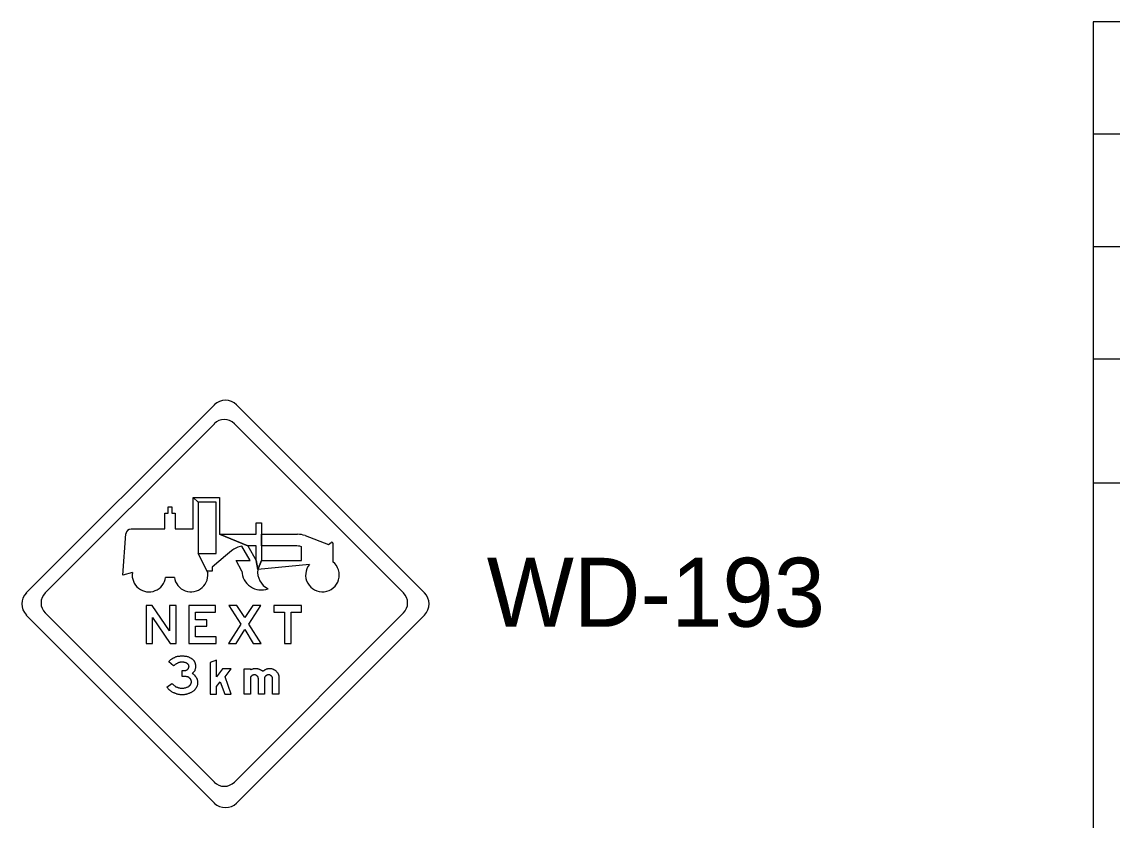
# Model space of a CAD drawing. Extents: x 1342 to 1558, y 178 to 457.
# Drawn here: x 1450.61 to 1485.03, y 224.55 to 249.75 of the extents above; entities that cross this region are included whole.
import ezdxf

# ---------------------------------------------------------------- set-up
doc = ezdxf.new("R2010")
doc.units = 0
for name, color, linetype in [('Level 1', 7, 'Continuous'), ('Level 10', 7, 'Continuous'), ('Level 44', 7, 'Continuous'), ('Level 63', 7, 'Continuous')]:
    doc.layers.add(name, color=color, linetype=linetype)

msp = doc.modelspace()

# ---------------------------------------------------------------- linework, layer by layer
at = {"layer": 'Level 1'}
for p, q in [((1484.439, 188.732), (1484.439, 235.196)), ((1455.229, 234.235), (1455.229, 234.439)), ((1455.229, 234.439), (1455.35, 234.439)), ((1455.35, 234.439), (1455.35, 234.235)), ((1456.018, 233.738), (1456.018, 234.733)), ((1456.018, 234.733), (1456.181, 234.582)), ((1456.181, 234.582), (1456.018, 234.733)), ((1456.018, 234.733), (1456.847, 234.733)), ((1456.181, 234.582), (1456.181, 232.966)), ((1456.743, 234.582), (1456.181, 234.582)), ((1456.743, 232.966), (1456.743, 234.582)), ((1456.847, 234.733), (1456.847, 233.571)), ((1455.122, 233.738), (1455.122, 234.235)), ((1455.122, 234.235), (1455.229, 234.235)), ((1455.35, 234.235), (1455.454, 234.235)), ((1455.454, 234.235), (1455.454, 233.738)), ((1454.063, 233.738), (1455.122, 233.738)), ((1455.454, 233.738), (1456.018, 233.738)), ((1458.01, 233.571), (1458.01, 233.93)), ((1458.01, 233.93), (1458.175, 233.93)), ((1458.175, 233.93), (1458.175, 233.571)), ((1453.795, 232.285), (1453.897, 233.585)), ((1456.847, 233.571), (1457.744, 233.202)), ((1457.744, 233.202), (1456.847, 233.571)), ((1456.847, 233.571), (1458.01, 233.571)), ((1458.175, 233.206), (1458.175, 233.571)), ((1458.175, 233.571), (1459.314, 233.571)), ((1458.175, 233.571), (1458.175, 233.206)), ((1459.55, 233.528), (1460.295, 233.244)), ((1457.232, 233.051), (1457.036, 232.887)), ((1457.818, 232.742), (1457.555, 233.198)), ((1458.01, 233.206), (1457.741, 233.206)), ((1457.741, 233.206), (1457.744, 233.202)), ((1457.744, 233.202), (1458.01, 232.742)), ((1458.01, 232.742), (1458.01, 233.206)), ((1459.246, 233.206), (1458.175, 233.206)), ((1458.175, 233.206), (1458.175, 232.742)), ((1459.436, 232.742), (1459.436, 233.181)), ((1460.295, 233.244), (1460.377, 233.312)), ((1460.431, 233.286), (1460.431, 232.7)), ((1456.181, 232.966), (1456.477, 232.359)), ((1456.477, 232.359), (1456.181, 232.966)), ((1456.181, 232.966), (1456.743, 232.966)), ((1457.036, 232.887), (1456.615, 232.533)), ((1457.554, 232.41), (1457.371, 232.742)), ((1457.371, 232.742), (1457.818, 232.742)), ((1458.01, 232.742), (1458.055, 232.459)), ((1458.055, 232.459), (1458.01, 232.742)), ((1458.055, 232.459), (1458.175, 232.742)), ((1458.175, 232.742), (1458.055, 232.459)), ((1458.175, 232.742), (1459.436, 232.742)), ((1454.099, 232.363), (1453.795, 232.285)), ((1456.615, 232.41), (1456.468, 232.41)), ((1456.615, 232.533), (1456.615, 232.41)), ((1459.687, 232.62), (1458.055, 232.459)), ((1455.426, 232.211), (1455.15, 232.211))]:
    msp.add_line(p, q, dxfattribs=at)
for points in [[(1454.531, 231.319), (1454.531, 230.124), (1454.738, 230.124), (1454.738, 230.943), (1455.293, 230.124), (1455.481, 230.124), (1455.481, 231.319), (1455.274, 231.319), (1455.274, 230.52), (1454.729, 231.319), (1454.531, 231.319)], [(1455.886, 231.319), (1455.886, 230.124), (1456.741, 230.124), (1456.741, 230.331), (1456.093, 230.331), (1456.093, 230.67), (1456.45, 230.67), (1456.45, 230.868), (1456.093, 230.868), (1456.093, 231.112), (1456.722, 231.112), (1456.722, 231.319), (1455.886, 231.319)], [(1457.146, 231.319), (1457.522, 230.736), (1457.136, 230.124), (1457.381, 230.124), (1457.653, 230.567), (1457.917, 230.124), (1458.161, 230.124), (1457.776, 230.736), (1458.152, 231.319), (1457.898, 231.319), (1457.653, 230.943), (1457.399, 231.319), (1457.146, 231.319)], [(1458.566, 231.319), (1458.566, 231.112), (1458.904, 231.112), (1458.904, 230.124), (1459.111, 230.124), (1459.111, 231.112), (1459.441, 231.112), (1459.441, 231.319), (1458.566, 231.319)], [(1455.247, 229.55), (1455.257, 229.569), (1455.275, 229.578), (1455.285, 229.587), (1455.304, 229.607), (1455.313, 229.616), (1455.332, 229.625), (1455.35, 229.635), (1455.36, 229.644), (1455.379, 229.663), (1455.398, 229.673), (1455.416, 229.673), (1455.426, 229.682), (1455.445, 229.691), (1455.463, 229.7), (1455.482, 229.71), (1455.501, 229.71), (1455.52, 229.719), (1455.539, 229.719), (1455.557, 229.728), (1455.576, 229.728), (1455.595, 229.728), (1455.614, 229.738), (1455.633, 229.738), (1455.652, 229.738), (1455.67, 229.738), (1455.689, 229.738), (1455.708, 229.738), (1455.727, 229.738), (1455.745, 229.728), (1455.764, 229.728), (1455.783, 229.728), (1455.802, 229.719), (1455.811, 229.719), (1455.83, 229.71), (1455.849, 229.71), (1455.868, 229.7), (1455.887, 229.691), (1455.905, 229.682), (1455.924, 229.673), (1455.934, 229.673), (1455.952, 229.663)], [(1455.952, 229.663), (1455.962, 229.653), (1455.98, 229.644), (1455.99, 229.635), (1456, 229.625), (1456.009, 229.616), (1456.018, 229.607), (1456.028, 229.597), (1456.037, 229.587), (1456.046, 229.578), (1456.046, 229.559), (1456.056, 229.55), (1456.066, 229.541), (1456.075, 229.531), (1456.075, 229.512), (1456.084, 229.503), (1456.084, 229.484), (1456.084, 229.475), (1456.093, 229.466), (1456.093, 229.446), (1456.093, 229.437), (1456.093, 229.418), (1456.093, 229.409), (1456.093, 229.39), (1456.093, 229.38), (1456.093, 229.362), (1456.093, 229.352), (1456.093, 229.343), (1456.084, 229.324), (1456.084, 229.314), (1456.075, 229.296), (1456.075, 229.287), (1456.066, 229.277), (1456.066, 229.259), (1456.056, 229.249), (1456.046, 229.239), (1456.037, 229.23), (1456.028, 229.221), (1456.018, 229.202), (1456.009, 229.193), (1456, 229.183), (1455.99, 229.173)], [(1455.398, 229.418), (1455.247, 229.55)], [(1455.811, 229.503), (1455.793, 229.512), (1455.783, 229.512), (1455.764, 229.521), (1455.755, 229.521), (1455.736, 229.521), (1455.727, 229.531), (1455.708, 229.531), (1455.698, 229.531), (1455.68, 229.531), (1455.67, 229.531), (1455.652, 229.531), (1455.633, 229.531), (1455.623, 229.531), (1455.604, 229.531), (1455.595, 229.521), (1455.576, 229.521), (1455.567, 229.521), (1455.548, 229.512), (1455.539, 229.503), (1455.52, 229.503), (1455.511, 229.494), (1455.492, 229.484), (1455.482, 229.484), (1455.473, 229.475), (1455.454, 229.466), (1455.445, 229.456), (1455.435, 229.446), (1455.426, 229.437), (1455.416, 229.428), (1455.398, 229.418)], [(1455.793, 229.08), (1455.67, 229.08), (1455.67, 229.277), (1455.764, 229.277)], [(1455.764, 229.277), (1455.774, 229.277), (1455.783, 229.277), (1455.793, 229.287), (1455.802, 229.287), (1455.811, 229.287), (1455.821, 229.296), (1455.83, 229.296), (1455.839, 229.305), (1455.849, 229.314), (1455.849, 229.324), (1455.859, 229.324), (1455.868, 229.334), (1455.868, 229.343), (1455.868, 229.352), (1455.877, 229.352), (1455.877, 229.362), (1455.877, 229.371), (1455.877, 229.38), (1455.877, 229.39), (1455.887, 229.4), (1455.877, 229.409), (1455.877, 229.418), (1455.877, 229.428), (1455.877, 229.437), (1455.868, 229.446), (1455.868, 229.456), (1455.859, 229.456), (1455.859, 229.466), (1455.849, 229.475), (1455.849, 229.484), (1455.839, 229.484), (1455.83, 229.494), (1455.821, 229.494), (1455.821, 229.503), (1455.811, 229.503)], [(1456.752, 229.597), (1456.555, 229.521), (1456.555, 228.525), (1456.752, 228.525), (1456.752, 228.769), (1456.874, 228.911), (1457.015, 228.525), (1457.222, 228.525), (1457.024, 229.07), (1457.222, 229.324), (1456.949, 229.324), (1456.752, 229.07), (1456.752, 229.597)], [(1457.824, 229.014), (1457.824, 228.525), (1457.626, 228.525), (1457.626, 229.324), (1457.824, 229.324), (1457.824, 229.296)], [(1457.824, 229.296), (1457.843, 229.305), (1457.852, 229.305), (1457.871, 229.314), (1457.881, 229.314), (1457.899, 229.324), (1457.909, 229.324), (1457.927, 229.334), (1457.937, 229.334), (1457.956, 229.334), (1457.974, 229.334), (1457.984, 229.334), (1458.002, 229.334), (1458.022, 229.334), (1458.031, 229.334), (1458.05, 229.334), (1458.059, 229.324), (1458.078, 229.324), (1458.088, 229.324), (1458.106, 229.314), (1458.125, 229.305), (1458.134, 229.305), (1458.144, 229.296), (1458.163, 229.287), (1458.172, 229.287), (1458.191, 229.277), (1458.2, 229.268), (1458.209, 229.259), (1458.219, 229.249)], [(1458.219, 229.249), (1458.238, 229.259), (1458.247, 229.268), (1458.257, 229.277), (1458.266, 229.287), (1458.275, 229.287), (1458.285, 229.296), (1458.295, 229.305), (1458.313, 229.305), (1458.323, 229.314), (1458.332, 229.324), (1458.35, 229.324), (1458.36, 229.324), (1458.379, 229.334), (1458.388, 229.334), (1458.398, 229.334), (1458.416, 229.334), (1458.426, 229.334), (1458.445, 229.334), (1458.454, 229.334), (1458.473, 229.334), (1458.482, 229.334), (1458.492, 229.334), (1458.511, 229.324), (1458.52, 229.324), (1458.53, 229.324), (1458.548, 229.314), (1458.557, 229.305), (1458.567, 229.305), (1458.586, 229.296), (1458.595, 229.287), (1458.605, 229.287), (1458.614, 229.277), (1458.623, 229.268), (1458.633, 229.259), (1458.643, 229.249), (1458.652, 229.239), (1458.661, 229.221), (1458.671, 229.211), (1458.68, 229.202), (1458.689, 229.193), (1458.689, 229.183), (1458.699, 229.164), (1458.699, 229.155), (1458.708, 229.145), (1458.708, 229.127), (1458.718, 229.118), (1458.718, 229.108), (1458.718, 229.089), (1458.718, 229.08)], [(1455.99, 229.173), (1456.009, 229.173), (1456.018, 229.164), (1456.028, 229.155), (1456.037, 229.145), (1456.046, 229.136), (1456.066, 229.127), (1456.075, 229.108), (1456.084, 229.098), (1456.093, 229.089), (1456.093, 229.08), (1456.103, 229.07), (1456.112, 229.052), (1456.121, 229.042), (1456.121, 229.023), (1456.131, 229.014), (1456.141, 229.004), (1456.141, 228.986), (1456.141, 228.976), (1456.15, 228.957), (1456.15, 228.948), (1456.15, 228.929), (1456.15, 228.911), (1456.15, 228.901), (1456.15, 228.882), (1456.15, 228.873), (1456.15, 228.854), (1456.15, 228.845), (1456.15, 228.826), (1456.15, 228.816), (1456.141, 228.797), (1456.141, 228.788), (1456.131, 228.769), (1456.131, 228.76), (1456.121, 228.741), (1456.112, 228.732), (1456.112, 228.722), (1456.103, 228.704), (1456.093, 228.694), (1456.084, 228.685), (1456.075, 228.675), (1456.066, 228.666), (1456.056, 228.647), (1456.046, 228.638), (1456.037, 228.628), (1456.018, 228.619), (1456.009, 228.609), (1455.99, 228.6), (1455.971, 228.591), (1455.952, 228.581), (1455.943, 228.572), (1455.924, 228.562), (1455.905, 228.553), (1455.887, 228.544), (1455.868, 228.544), (1455.849, 228.534), (1455.83, 228.525), (1455.811, 228.525), (1455.793, 228.515), (1455.774, 228.515), (1455.755, 228.515), (1455.736, 228.506), (1455.717, 228.506), (1455.698, 228.506), (1455.68, 228.506), (1455.661, 228.506), (1455.642, 228.506), (1455.623, 228.506), (1455.604, 228.506), (1455.586, 228.515), (1455.567, 228.515), (1455.548, 228.515), (1455.52, 228.525), (1455.501, 228.525), (1455.492, 228.534), (1455.473, 228.544), (1455.454, 228.544), (1455.435, 228.553), (1455.416, 228.562), (1455.398, 228.572), (1455.379, 228.581), (1455.36, 228.591), (1455.35, 228.6), (1455.332, 228.609), (1455.313, 228.619), (1455.304, 228.628), (1455.285, 228.647), (1455.266, 228.656), (1455.257, 228.666), (1455.238, 228.685), (1455.228, 228.694), (1455.219, 228.713), (1455.2, 228.732), (1455.191, 228.741)], [(1455.896, 228.788), (1455.905, 228.797), (1455.915, 228.797), (1455.924, 228.807), (1455.924, 228.816), (1455.934, 228.826), (1455.943, 228.835), (1455.943, 228.845), (1455.943, 228.854), (1455.952, 228.863), (1455.952, 228.873), (1455.952, 228.882), (1455.962, 228.891), (1455.962, 228.901), (1455.962, 228.911), (1455.962, 228.92), (1455.962, 228.929), (1455.962, 228.938), (1455.952, 228.948), (1455.952, 228.957), (1455.952, 228.967), (1455.943, 228.976), (1455.943, 228.986), (1455.934, 228.995), (1455.934, 229.004), (1455.924, 229.014), (1455.924, 229.023), (1455.915, 229.023), (1455.905, 229.032), (1455.896, 229.042), (1455.887, 229.042), (1455.887, 229.052), (1455.877, 229.061), (1455.868, 229.061), (1455.859, 229.061), (1455.849, 229.07), (1455.839, 229.07), (1455.83, 229.07), (1455.821, 229.07), (1455.802, 229.08), (1455.793, 229.08)], [(1458.078, 229.014), (1458.078, 229.023), (1458.068, 229.032), (1458.068, 229.042), (1458.068, 229.052), (1458.068, 229.061), (1458.059, 229.07), (1458.059, 229.08), (1458.05, 229.089), (1458.04, 229.098), (1458.031, 229.108), (1458.022, 229.118), (1458.012, 229.127), (1458.002, 229.127), (1457.993, 229.127), (1457.984, 229.136), (1457.974, 229.136), (1457.965, 229.136), (1457.956, 229.136), (1457.947, 229.136), (1457.937, 229.136), (1457.927, 229.136), (1457.918, 229.136), (1457.909, 229.127), (1457.899, 229.127), (1457.89, 229.127), (1457.881, 229.118), (1457.871, 229.118), (1457.871, 229.108), (1457.861, 229.098), (1457.852, 229.098), (1457.852, 229.089), (1457.843, 229.08), (1457.843, 229.07), (1457.833, 229.07), (1457.833, 229.061), (1457.833, 229.052), (1457.824, 229.042), (1457.824, 229.032), (1457.824, 229.023), (1457.824, 229.014)], [(1458.275, 229.014), (1458.275, 228.525), (1458.078, 228.525), (1458.078, 229.014)], [(1458.52, 229.014), (1458.52, 229.023), (1458.52, 229.032), (1458.52, 229.042), (1458.52, 229.052), (1458.511, 229.061), (1458.511, 229.07), (1458.502, 229.08), (1458.502, 229.089), (1458.492, 229.098), (1458.482, 229.098), (1458.482, 229.108), (1458.473, 229.118), (1458.464, 229.118), (1458.454, 229.127), (1458.445, 229.127), (1458.436, 229.136), (1458.426, 229.136), (1458.416, 229.136), (1458.407, 229.136), (1458.398, 229.136), (1458.388, 229.136), (1458.379, 229.136), (1458.37, 229.136), (1458.36, 229.136), (1458.35, 229.127), (1458.341, 229.127), (1458.332, 229.118), (1458.323, 229.118), (1458.313, 229.108), (1458.313, 229.098), (1458.304, 229.098), (1458.295, 229.089), (1458.295, 229.08), (1458.285, 229.07), (1458.285, 229.061), (1458.275, 229.052), (1458.275, 229.042), (1458.275, 229.032), (1458.275, 229.023), (1458.275, 229.014)], [(1458.718, 229.08), (1458.718, 228.525), (1458.52, 228.525), (1458.52, 229.014)], [(1455.191, 228.741), (1455.35, 228.863)], [(1455.35, 228.863), (1455.36, 228.854), (1455.379, 228.845), (1455.388, 228.835), (1455.398, 228.816), (1455.407, 228.807), (1455.416, 228.797), (1455.435, 228.788), (1455.445, 228.779), (1455.454, 228.769), (1455.473, 228.76), (1455.482, 228.76), (1455.501, 228.75), (1455.511, 228.741), (1455.529, 228.741), (1455.539, 228.732), (1455.557, 228.722), (1455.576, 228.722), (1455.586, 228.722), (1455.604, 228.713), (1455.623, 228.713), (1455.633, 228.713), (1455.652, 228.713), (1455.67, 228.713), (1455.68, 228.713), (1455.698, 228.713), (1455.717, 228.713), (1455.727, 228.713), (1455.745, 228.722), (1455.755, 228.722), (1455.774, 228.722), (1455.793, 228.732), (1455.802, 228.732), (1455.821, 228.741), (1455.83, 228.75), (1455.849, 228.76), (1455.859, 228.76), (1455.877, 228.769), (1455.887, 228.779), (1455.896, 228.788)]]:
    msp.add_lwpolyline(points, dxfattribs=at)
for centre, radius, start, end in [((1454.063, 233.571), 0.166, 90, 175.4844), ((1459.314, 232.908), 0.664, 69.1426, 90), ((1457.658, 232.543), 0.664, 98.9934, 130.002), ((1459.247, 232.543), 0.664, 73.4264, 90), ((1460.398, 233.286), 0.0332, 0, 129.522), ((1454.624, 232.285), 0.531, 171.5721, 351.9595), ((1455.952, 232.285), 0.531, 188.0405, 13.6001), ((1458.173, 232.434), 0.619, 182.1917, 289.6612), ((1458.665, 232.394), 0.613, 173.8894, 242.4775), ((1460.1, 232.285), 0.531, 140.9637, 51.3178)]:
    msp.add_arc(centre, radius, start, end, dxfattribs=at)
at = {"layer": 'Level 44'}
for p, q in [((1548.312, 249.746), (1484.432, 249.746)), ((1548.312, 246.197), (1484.432, 246.197)), ((1548.312, 242.648), (1484.432, 242.648)), ((1548.312, 239.1), (1484.432, 239.1)), ((1456.688, 237.656), (1450.751, 231.726)), ((1463.32, 231.726), (1457.39, 237.656)), ((1451.344, 231.722), (1456.688, 237.058)), ((1457.318, 237.058), (1462.656, 231.722)), ((1484.439, 235.196), (1548.312, 235.196)), ((1450.751, 231.022), (1456.688, 225.086)), ((1450.754, 231.022), (1450.751, 231.022)), ((1456.688, 225.746), (1451.344, 231.087)), ((1462.656, 231.087), (1457.318, 225.746)), ((1457.39, 225.086), (1463.32, 231.022))]:
    msp.add_line(p, q, dxfattribs=at)
for centre, radius, start, end in [((1457.037, 237.306), 0.497, 45, 135), ((1457.002, 236.743), 0.447, 45, 135), ((1451.105, 231.373), 0.497, 135, 225), ((1451.663, 231.403), 0.447, 135, 225), ((1462.341, 231.403), 0.447, 315, 45), ((1462.97, 231.373), 0.497, 315, 45), ((1457.002, 226.064), 0.447, 225, 315), ((1457.037, 225.441), 0.497, 225, 315)]:
    msp.add_arc(centre, radius, start, end, dxfattribs=at)
at = {"layer": 'Level 63'}
for p, q in [((1484.439, 243.274), (1484.439, 249.746)), ((1484.439, 235.196), (1484.439, 243.274))]:
    msp.add_line(p, q, dxfattribs=at)

# ---------------------------------------------------------------- texts
at = {"layer": 'Level 10'}
msp.add_text('WD-193', height=2.177, dxfattribs=at).set_placement((1465.289, 230.653))

doc.saveas('drawing.dxf')
